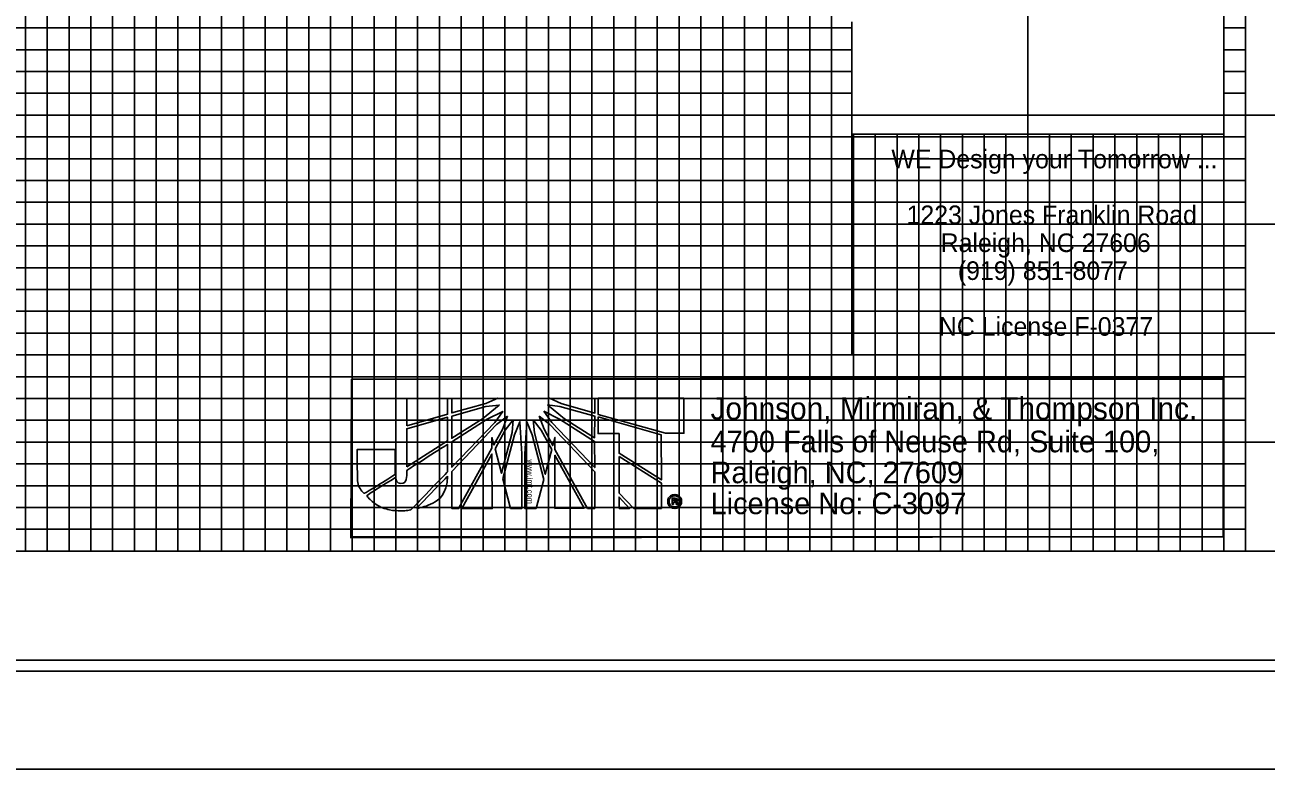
# Model space of a CAD drawing. Extents: x 557032 to 558840, y 515971 to 517218.
# Drawn here: x 558369.3 to 558654.2, y 516118.2 to 516288.9 of the extents above; entities that cross this region are included whole.
import ezdxf

# ---------------------------------------------------------------- set-up
doc = ezdxf.new("R2010")
doc.units = 0
for name, color, linetype in [('Prop DSN Text', 7, 'Continuous'), ('Prop Vertical Profile Grade Label', 7, 'Continuous'), ('Prop VPI Label', 7, 'Continuous'), ('Scratch_Level_5', 7, 'Continuous'), ('Sheet Cutting Line CELL', 7, 'Continuous'), ('Sheet DOT Grid CELL', 7, 'Continuous'), ('Sheet Layout Profile Border Port 2', 7, 'Continuous'), ('Sheet Plot Border Inside CELL', 7, 'Continuous'), ('Sheet Plot Border Outside CELL', 7, 'Continuous'), ('Sheet Profile CELL', 7, 'Continuous'), ('Sheet Profile Grid Major CELL', 7, 'Continuous'), ('Sheet Profile Grid Middle CELL', 7, 'Continuous'), ('Sheet Profile Grid Minor CELL', 7, 'Continuous')]:
    doc.layers.add(name, color=color, linetype=linetype)

msp = doc.modelspace()

# ---------------------------------------------------------------- linework, layer by layer
at = {"layer": 'Prop DSN Text'}
for p, q in [((558559.12, 516213.17), (558559.12, 516289.56)), ((558644.45, 516289.56), (558644.45, 516213.17)), ((558559.12, 516263.76), (558644.45, 516263.76)), ((558644.45, 516213.17), (558559.12, 516213.17))]:
    msp.add_line(p, q, dxfattribs=at)
at = {"layer": 'Prop Vertical Profile Grade Label'}
msp.add_lwpolyline([(558559.12, 516263.76), (558644.45, 516263.76), (558644.45, 516213.17), (558559.12, 516213.17)], close=True, dxfattribs=at)
at = {"layer": 'Prop VPI Label'}
for p, q in [((558466.31, 516203.16), (558456.95, 516203.15)), ((558456.95, 516203.15), (558456.95, 516196.94)), ((558466.31, 516199.54), (558466.31, 516203.16)), ((558477.82, 516203.21), (558467.28, 516203.2)), ((558467.28, 516203.2), (558467.28, 516199.85)), ((558467.28, 516199.85), (558475.13, 516202.02)), ((558475.13, 516202.02), (558477.82, 516203.21)), ((558500.12, 516203.19), (558489.74, 516203.22)), ((558489.74, 516203.22), (558492.37, 516201.99)), ((558492.37, 516201.99), (558500.13, 516199.82)), ((558500.13, 516199.82), (558500.12, 516203.19)), ((558520.53, 516203.25), (558500.85, 516203.24)), ((558500.85, 516203.24), (558500.85, 516199.62)), ((558520.54, 516195.19), (558520.53, 516203.25)), ((558456.95, 516196.94), (558466.31, 516199.54)), ((558475.13, 516201.3), (558467.29, 516199.13)), ((558467.29, 516199.13), (558467.29, 516194.06)), ((558474.31, 516198.51), (558478.19, 516201.67)), ((558478.19, 516201.67), (558475.13, 516201.3)), ((558478.96, 516200.22), (558475.4, 516198.41)), ((558477.16, 516197.68), (558478.96, 516200.22)), ((558480.05, 516199.09), (558477.56, 516197.17)), ((558478.9, 516196.09), (558480.05, 516199.09)), ((558487.31, 516199.1), (558488.45, 516196.1)), ((558489.79, 516197.18), (558487.31, 516199.1)), ((558488.4, 516200.23), (558490.21, 516197.65)), ((558492.02, 516198.42), (558488.4, 516200.23)), ((558489.22, 516201.68), (558493.15, 516198.47)), ((558492.11, 516201.31), (558489.22, 516201.68)), ((558500.13, 516199.11), (558492.11, 516201.31)), ((558500.07, 516194.15), (558500.13, 516199.11)), ((558500.85, 516199.62), (558500.85, 516199.51)), ((558500.85, 516199.51), (558516.35, 516195.19)), ((558500.85, 516198.96), (558500.85, 516198.89)), ((558515.36, 516194.83), (558500.85, 516198.96)), ((558466.31, 516198.86), (558456.95, 516196.23)), ((558456.95, 516196.23), (558456.96, 516187.5)), ((558466.32, 516193.44), (558466.31, 516198.86)), ((558467.29, 516194.06), (558474.31, 516198.51)), ((558475.4, 516198.41), (558467.29, 516193.24)), ((558467.3, 516187.4), (558477.16, 516197.68)), ((558477.56, 516197.17), (558467.3, 516186.41)), ((558476.95, 516192.52), (558478.9, 516196.09)), ((558481.39, 516198.26), (558479.54, 516195.88)), ((558481.13, 516195.37), (558481.39, 516198.26)), ((558482.93, 516197.84), (558481.66, 516194.84)), ((558483.34, 516190.46), (558482.93, 516197.84)), ((558484.48, 516197.84), (558484.01, 516190.46)), ((558485.72, 516194.85), (558484.48, 516197.84)), ((558485.98, 516198.26), (558486.29, 516195.27)), ((558487.79, 516195.89), (558485.98, 516198.26)), ((558488.45, 516196.1), (558490.46, 516192.38)), ((558500.08, 516186.35), (558489.79, 516197.18)), ((558490.21, 516197.65), (558500.08, 516187.32)), ((558500.07, 516193.32), (558492.02, 516198.42)), ((558493.15, 516198.47), (558500.07, 516194.15)), ((558500.85, 516198.89), (558500.86, 516195.13)), ((558456.96, 516187.5), (558466.32, 516193.44)), ((558467.29, 516193.24), (558467.3, 516187.4)), ((558476.48, 516191.75), (558476.48, 516194.22)), ((558476.48, 516194.22), (558476.95, 516192.52)), ((558479.54, 516195.88), (558477.21, 516191.64)), ((558478.71, 516186.02), (558481.13, 516195.37)), ((558481.66, 516194.84), (558479.02, 516184.72)), ((558488.42, 516184.58), (558485.72, 516194.85)), ((558486.29, 516195.27), (558488.72, 516185.81)), ((558490.22, 516191.5), (558487.79, 516195.89)), ((558490.46, 516192.38), (558490.94, 516194.24)), ((558490.94, 516194.24), (558490.94, 516191.5)), ((558500.08, 516187.32), (558500.07, 516193.32)), ((558500.86, 516195.13), (558505.66, 516195.13)), ((558505.66, 516195.13), (558505.67, 516190.63)), ((558515.37, 516184.5), (558515.36, 516194.83)), ((558516.35, 516195.19), (558520.54, 516195.19)), ((558468.85, 516177.92), (558476.48, 516191.75)), ((558476.48, 516190.41), (558469.58, 516177.92)), ((558476.56, 516177.92), (558476.48, 516190.41)), ((558477.21, 516191.64), (558478.71, 516186.02)), ((558483.36, 516177.98), (558483.34, 516190.46)), ((558484.01, 516190.46), (558484.02, 516177.98)), ((558488.72, 516185.81), (558490.22, 516191.5)), ((558490.94, 516191.5), (558498.43, 516177.95)), ((558505.67, 516190.63), (558515.37, 516184.5)), ((558497.66, 516177.99), (558490.94, 516190.16)), ((558490.94, 516190.16), (558490.96, 516177.98)), ((558505.67, 516189.86), (558505.67, 516181.49)), ((558515.37, 516183.77), (558505.67, 516189.86)), ((558467.3, 516186.41), (558467.31, 516177.92)), ((558479.02, 516184.72), (558480.79, 516177.97)), ((558500.09, 516177.95), (558500.08, 516186.35)), ((558486.61, 516177.98), (558488.42, 516184.58)), ((558515.38, 516177.96), (558515.37, 516183.77)), ((558505.67, 516181.49), (558509.03, 516177.96)), ((558508.1, 516177.95), (558505.67, 516180.58)), ((558505.67, 516180.58), (558505.68, 516177.95)), ((558517.84, 516178.85), (558517.84, 516180.28)), ((558517.84, 516180.28), (558518.43, 516180.28)), ((558518.43, 516180.01), (558518.17, 516180.01)), ((558518.17, 516180.01), (558518.17, 516179.67)), ((558518.17, 516179.67), (558518.43, 516179.67)), ((558518.43, 516179.41), (558518.17, 516179.41)), ((558518.17, 516179.41), (558518.17, 516178.85)), ((558518.43, 516181.12), (558518.43, 516180.83)), ((558518.43, 516180.83), (558518.43, 516181.12)), ((558518.43, 516180.28), (558518.43, 516180.01)), ((558518.43, 516180.01), (558518.43, 516180.28)), ((558518.43, 516180.28), (558518.52, 516180.28)), ((558518.47, 516180.01), (558518.43, 516180.01)), ((558518.43, 516179.67), (558518.43, 516179.41)), ((558518.43, 516179.41), (558518.43, 516179.67)), ((558518.43, 516179.67), (558518.44, 516179.67)), ((558518.44, 516179.41), (558518.43, 516179.41)), ((558467.31, 516177.92), (558468.85, 516177.92)), ((558469.58, 516177.92), (558476.56, 516177.92)), ((558480.79, 516177.97), (558483.36, 516177.98)), ((558484.02, 516177.98), (558486.61, 516177.98)), ((558490.96, 516177.98), (558497.66, 516177.99)), ((558498.43, 516177.95), (558500.09, 516177.95)), ((558505.68, 516177.95), (558508.1, 516177.95)), ((558509.03, 516177.96), (558515.38, 516177.96)), ((558518.17, 516178.85), (558517.84, 516178.85)), ((558518.43, 516178.29), (558518.43, 516177.98)), ((558518.43, 516177.98), (558518.43, 516178.29)), ((558518.43, 516178.29), (558518.44, 516178.29)), ((558518.44, 516177.98), (558518.43, 516177.98))]:
    msp.add_line(p, q, dxfattribs=at)
for points in [[(558444.29, 516207.58), (558644.45, 516207.98), (558644.32, 516171.48), (558444.14, 516171.2)], [(558444.29, 516171.48), (558644.32, 516171.48), (558644.32, 516207.58), (558444.29, 516207.58)]]:
    msp.add_lwpolyline(points, close=True, dxfattribs=at)
for points in [[(558456.95, 516196.94), (558466.31, 516199.54), (558466.31, 516203.16), (558456.95, 516203.15), (558456.95, 516196.94)], [(558475.13, 516202.02), (558477.82, 516203.21), (558467.28, 516203.2), (558467.28, 516199.85), (558475.13, 516202.02)], [(558492.37, 516201.99), (558500.13, 516199.82), (558500.12, 516203.19), (558489.74, 516203.22), (558492.37, 516201.99)], [(558520.53, 516203.25), (558500.85, 516203.24), (558500.85, 516199.62), (558500.85, 516199.51), (558516.35, 516195.19), (558520.54, 516195.19), (558520.53, 516203.25)], [(558467.29, 516199.13), (558467.29, 516194.06), (558474.31, 516198.51), (558478.19, 516201.67), (558475.13, 516201.3), (558467.29, 516199.13)], [(558467.29, 516193.24), (558467.3, 516187.4), (558477.16, 516197.68), (558478.96, 516200.22), (558475.4, 516198.41), (558467.29, 516193.24)], [(558480.05, 516199.09), (558477.56, 516197.17), (558467.3, 516186.41), (558467.31, 516177.92), (558468.85, 516177.92), (558476.48, 516191.75), (558476.48, 516194.22), (558476.95, 516192.52), (558478.9, 516196.09), (558480.05, 516199.09)], [(558487.31, 516199.1), (558488.45, 516196.1), (558490.46, 516192.38), (558490.94, 516194.24), (558490.94, 516191.5), (558498.43, 516177.95), (558500.09, 516177.95), (558500.08, 516186.35), (558489.79, 516197.18), (558487.31, 516199.1)], [(558488.4, 516200.23), (558490.21, 516197.65), (558500.08, 516187.32), (558500.07, 516193.32), (558492.02, 516198.42), (558488.4, 516200.23)], [(558489.22, 516201.68), (558493.15, 516198.47), (558500.07, 516194.15), (558500.13, 516199.11), (558492.11, 516201.31), (558489.22, 516201.68)], [(558500.85, 516198.96), (558500.85, 516198.89), (558500.86, 516195.13), (558505.66, 516195.13), (558505.67, 516190.63), (558515.37, 516184.5), (558515.36, 516194.83), (558500.85, 516198.96)], [(558456.96, 516187.5), (558466.32, 516193.44), (558466.31, 516198.86), (558456.95, 516196.23), (558456.96, 516187.5)], [(558481.39, 516198.26), (558479.54, 516195.88), (558477.21, 516191.64), (558478.71, 516186.02), (558481.13, 516195.37), (558481.39, 516198.26)], [(558481.66, 516194.84), (558479.02, 516184.72), (558480.79, 516177.97), (558483.36, 516177.98), (558483.34, 516190.46), (558482.93, 516197.84), (558481.66, 516194.84)], [(558484.48, 516197.84), (558484.01, 516190.46), (558484.02, 516177.98), (558486.61, 516177.98), (558488.42, 516184.58), (558485.72, 516194.85), (558484.48, 516197.84)], [(558485.98, 516198.26), (558486.29, 516195.27), (558488.72, 516185.81), (558490.22, 516191.5), (558487.79, 516195.89), (558485.98, 516198.26)], [(558469.58, 516177.92), (558476.56, 516177.92), (558476.48, 516190.41), (558469.58, 516177.92)], [(558490.96, 516177.98), (558497.66, 516177.99), (558490.94, 516190.16), (558490.96, 516177.98)], [(558505.67, 516189.86), (558505.67, 516181.49), (558509.03, 516177.96), (558515.38, 516177.96), (558515.37, 516183.77), (558505.67, 516189.86), (558505.67, 516189.86)], [(558505.68, 516177.95), (558505.68, 516177.95), (558508.1, 516177.95), (558505.67, 516180.58), (558505.68, 516177.95)], [(558519.05, 516179.19), (558519.05, 516179.11), (558519.06, 516179.06), (558519.06, 516179), (558519.1, 516178.85), (558518.81, 516178.85)]]:
    msp.add_lwpolyline(points, dxfattribs=at)
for points, degree in [([(558454.27, 516191.51), (558454.27, 516191.51), (558445.6, 516191.5), (558445.6, 516191.5), (558445.6, 516191.5), (558445.61, 516186.08), (558445.61, 516186.08), (558445.61, 516186.08), (558445.61, 516185.51), (558445.61, 516185.51), (558445.61, 516183.81), (558446.17, 516182.47), (558447.16, 516181.34), (558447.16, 516181.34), (558454.28, 516185.67), (558454.28, 516185.78), (558454.28, 516185.78), (558454.27, 516191.51), (558454.27, 516191.51)], 3), ([(558455.62, 516183.71), (558455.07, 516183.71), (558454.59, 516184.02), (558454.38, 516185.06), (558454.38, 516185.06), (558447.67, 516180.89), (558447.67, 516180.89), (558449.74, 516178.72), (558453.05, 516177.42), (558455.84, 516177.43), (558456.57, 516177.43), (558457.13, 516177.49), (558457.9, 516177.64), (558457.9, 516177.64), (558466.32, 516186.36), (558466.32, 516186.36), (558466.32, 516186.36), (558466.32, 516192.67), (558466.32, 516192.67), (558466.32, 516192.67), (558456.96, 516186.71), (558456.96, 516186.71), (558456.96, 516184.35), (558456.39, 516183.71), (558455.62, 516183.71)], 3), ([(558455.62, 516183.71), (558455.07, 516183.71), (558454.59, 516184.02), (558454.38, 516185.06), (558454.38, 516185.06), (558447.67, 516180.89), (558447.67, 516180.89), (558449.74, 516178.72), (558453.05, 516177.42), (558455.84, 516177.43), (558456.57, 516177.43), (558457.13, 516177.49), (558457.9, 516177.64), (558457.9, 516177.64), (558466.32, 516186.36), (558466.32, 516186.36), (558466.32, 516186.36), (558466.32, 516192.67), (558466.32, 516192.67), (558466.32, 516192.67), (558456.96, 516186.71), (558456.96, 516186.71), (558456.96, 516184.35), (558456.39, 516183.71), (558455.62, 516183.71)], 3), ([(558466.33, 516185.38), (558466.33, 516185.38), (558459.04, 516177.85), (558459.04, 516177.85), (558462.61, 516178.73), (558466.16, 516181.1), (558466.33, 516185.38)], 3), ([(558518.43, 516177.98), (558518, 516177.98), (558517.62, 516178.13), (558517.31, 516178.44), (558517, 516178.74), (558516.84, 516179.12), (558516.84, 516179.56), (558516.84, 516180), (558517, 516180.38), (558517.31, 516180.67), (558517.62, 516180.97), (558517.98, 516181.12), (558518.43, 516181.12)], 3), ([(558518.43, 516180.83), (558518.07, 516180.83), (558517.78, 516180.71), (558517.53, 516180.47), (558517.28, 516180.23), (558517.15, 516179.91), (558517.15, 516179.56), (558517.15, 516179.21), (558517.28, 516178.9), (558517.53, 516178.65), (558517.78, 516178.41), (558518.08, 516178.29), (558518.43, 516178.29)], 3), ([(558518.43, 516181.12), (558518.87, 516181.13), (558519.25, 516180.97), (558519.56, 516180.67), (558519.87, 516180.38), (558520.03, 516180.01), (558520.03, 516179.57)], 3), ([(558518.44, 516178.29), (558518.79, 516178.29), (558519.09, 516178.41), (558519.34, 516178.65), (558519.59, 516178.9), (558519.72, 516179.21), (558519.72, 516179.56), (558519.71, 516179.92), (558519.58, 516180.23), (558519.34, 516180.48), (558519.09, 516180.71), (558518.79, 516180.83), (558518.43, 516180.83)], 3), ([(558518.44, 516179.67), (558518.65, 516179.67), (558518.75, 516179.73), (558518.75, 516179.85), (558518.75, 516179.95), (558518.66, 516180.01), (558518.47, 516180.01)], 3), ([(558520.03, 516179.57), (558520.03, 516179.12), (558519.87, 516178.75), (558519.57, 516178.43), (558519.26, 516178.13), (558518.88, 516177.98), (558518.44, 516177.98)], 3), ([(558518.69, 516179.36), (558518.65, 516179.38), (558518.57, 516179.41), (558518.44, 516179.41)], 2), ([(558518.52, 516180.28), (558518.88, 516180.28), (558519.06, 516180.14), (558519.06, 516179.85), (558519.06, 516179.72), (558519.01, 516179.62), (558518.9, 516179.54)], 3), ([(558518.81, 516178.85), (558518.77, 516178.93), (558518.74, 516179), (558518.74, 516179.11), (558518.74, 516179.24), (558518.73, 516179.32), (558518.69, 516179.36)], 3), ([(558518.9, 516179.54), (558518.99, 516179.49), (558519.04, 516179.37), (558519.05, 516179.19)], 2)]:
    msp.add_open_spline(points, degree=degree, dxfattribs=at)
at = {"layer": 'Scratch_Level_5'}
msp.add_lwpolyline([(558074.45, 516168.17), (558699.34, 516168.17), (558699.34, 516568.17), (558074.45, 516568.17)], close=True, dxfattribs=at)
at = {"layer": 'Sheet Cutting Line CELL'}
msp.add_line((557032.45, 516118.17), (558716.45, 516118.17), dxfattribs=at)
at = {"layer": 'Sheet DOT Grid CELL'}
for p, q in [((558399.45, 516668.17), (558399.45, 516168.17)), ((558449.45, 516668.17), (558449.45, 516168.17)), ((558499.45, 516668.17), (558499.45, 516168.17)), ((558549.45, 516668.17), (558549.45, 516168.17)), ((558599.45, 516668.17), (558599.45, 516168.17)), ((558649.45, 516668.17), (558649.45, 516168.17)), ((557199.45, 516268.17), (558699.34, 516268.17)), ((557199.45, 516218.17), (558699.34, 516218.17))]:
    msp.add_line(p, q, dxfattribs=at)
at = {"layer": 'Sheet Layout Profile Border Port 2'}
msp.add_lwpolyline([(557249.45, 516668.17), (558649.45, 516668.17), (558649.45, 516168.17), (557249.45, 516168.17)], close=True, dxfattribs=at)
at = {"layer": 'Sheet Plot Border Inside CELL'}
msp.add_lwpolyline([(557045.45, 516140.62), (558711.95, 516140.62), (558711.95, 517195.72), (557045.45, 517195.72)], close=True, dxfattribs=at)
at = {"layer": 'Sheet Plot Border Outside CELL'}
msp.add_lwpolyline([(557032.45, 516118.17), (558716.45, 516118.17), (558716.45, 517218.17), (557032.45, 517218.17)], close=True, dxfattribs=at)
at = {"layer": 'Sheet Profile CELL'}
for p, q in [((558699.45, 516168.17), (557199.45, 516168.17)), ((557199.45, 516143.17), (558699.45, 516143.17))]:
    msp.add_line(p, q, dxfattribs=at)
msp.add_lwpolyline([(558699.45, 517193.17), (557199.45, 517193.17), (557199.45, 516143.17), (558699.45, 516143.17)], close=True, dxfattribs=at)
at = {"layer": 'Sheet Profile Grid Major CELL'}
msp.add_line((558599.45, 516168.17), (558599.45, 516168.17), dxfattribs=at)
for points in [[(558349.45, 516168.17), (558399.45, 516168.17), (558399.45, 516668.17), (558449.45, 516668.17), (558449.45, 516168.17), (558499.45, 516168.17), (558499.45, 516668.17), (558549.45, 516668.17), (558549.45, 516168.17), (558599.45, 516168.17), (558599.45, 516168.17), (558599.45, 516263.76)], [(558599.45, 516289.56), (558599.45, 516668.17), (558649.45, 516668.17), (558649.45, 516168.17)], [(558559.12, 516268.17), (557199.45, 516268.17), (557199.45, 516268.17), (557199.45, 516218.17), (558699.45, 516218.17)], [(558699.45, 516268.17), (558644.45, 516268.17)], [(558699.45, 516168.17), (557199.45, 516168.17)]]:
    msp.add_lwpolyline(points, dxfattribs=at)
at = {"layer": 'Sheet Profile Grid Middle CELL'}
for p, q in [((558374.45, 516668.17), (558374.45, 516168.17)), ((558424.45, 516168.17), (558424.45, 516668.17)), ((558474.45, 516668.17), (558474.45, 516168.17)), ((558524.45, 516168.17), (558524.45, 516668.17)), ((558574.45, 516263.76), (558574.45, 516168.17)), ((558624.45, 516168.17), (558624.45, 516263.76)), ((558374.45, 516168.17), (558424.45, 516168.17)), ((558474.45, 516168.17), (558524.45, 516168.17)), ((558574.45, 516168.17), (558624.45, 516168.17))]:
    msp.add_line(p, q, dxfattribs=at)
for points in [[(558699.45, 516293.17), (557199.45, 516293.17), (557199.45, 516243.17), (558699.45, 516243.17)], [(558699.45, 516193.17), (557199.45, 516193.17)]]:
    msp.add_lwpolyline(points, dxfattribs=at)
at = {"layer": 'Sheet Profile Grid Minor CELL'}
for p, q in [((557249.45, 516288.17), (558559.12, 516288.17)), ((558644.45, 516288.17), (558649.45, 516288.17)), ((558559.12, 516283.17), (557249.45, 516283.17)), ((558649.45, 516283.17), (558644.45, 516283.17)), ((557249.45, 516278.17), (558559.12, 516278.17)), ((558644.45, 516278.17), (558649.45, 516278.17)), ((558559.12, 516273.17), (557249.45, 516273.17)), ((558649.45, 516273.17), (558644.45, 516273.17)), ((557249.45, 516263.17), (558649.45, 516263.17)), ((558649.45, 516258.17), (557249.45, 516258.17)), ((557249.45, 516253.17), (558649.45, 516253.17)), ((558649.45, 516248.17), (557249.45, 516248.17)), ((557249.45, 516238.17), (558649.45, 516238.17)), ((558649.45, 516233.17), (557249.45, 516233.17)), ((557249.45, 516228.17), (558649.45, 516228.17)), ((558649.45, 516223.17), (557249.45, 516223.17)), ((557249.45, 516213.17), (558649.45, 516213.17)), ((558649.45, 516208.17), (557249.45, 516208.17)), ((557249.45, 516203.17), (558649.45, 516203.17)), ((558649.45, 516198.17), (557249.45, 516198.17)), ((557249.45, 516188.17), (558649.45, 516188.17)), ((558649.45, 516183.17), (557249.45, 516183.17)), ((557249.45, 516178.17), (558649.45, 516178.17)), ((557249.45, 516173.17), (558649.45, 516173.17)), ((558649.45, 516173.17), (558649.45, 516173.17))]:
    msp.add_line(p, q, dxfattribs=at)
for points in [[(558364.45, 516168.17), (558369.45, 516168.17), (558369.45, 516668.17), (558379.45, 516668.17), (558379.45, 516168.17), (558384.45, 516168.17), (558384.45, 516668.17), (558389.45, 516668.17), (558389.45, 516168.17)], [(558389.45, 516168.17), (558394.45, 516168.17), (558394.45, 516668.17)], [(558404.45, 516668.17), (558404.45, 516168.17), (558409.45, 516168.17), (558409.45, 516668.17)], [(558414.45, 516668.17), (558414.45, 516168.17), (558419.45, 516168.17), (558419.45, 516668.17)], [(558429.45, 516668.17), (558429.45, 516168.17), (558434.45, 516168.17), (558434.45, 516668.17)], [(558439.45, 516668.17), (558439.45, 516168.17), (558444.45, 516168.17), (558444.45, 516668.17)], [(558454.45, 516668.17), (558454.45, 516168.17), (558459.45, 516168.17), (558459.45, 516668.17)], [(558464.45, 516668.17), (558464.45, 516168.17), (558469.45, 516168.17), (558469.45, 516668.17)], [(558479.45, 516668.17), (558479.45, 516168.17), (558484.45, 516168.17), (558484.45, 516668.17)], [(558489.45, 516668.17), (558489.45, 516168.17), (558494.45, 516168.17), (558494.45, 516668.17)], [(558504.45, 516668.17), (558504.45, 516168.17), (558509.45, 516168.17), (558509.45, 516668.17)], [(558514.45, 516668.17), (558514.45, 516168.17), (558519.45, 516168.17), (558519.45, 516668.17)], [(558529.45, 516668.17), (558529.45, 516168.17), (558534.45, 516168.17), (558534.45, 516668.17)], [(558539.45, 516668.17), (558539.45, 516168.17), (558544.45, 516168.17), (558544.45, 516668.17)], [(558554.45, 516668.17), (558554.45, 516168.17), (558559.45, 516168.17), (558559.45, 516263.76)], [(558639.45, 516263.76), (558639.45, 516168.17), (558644.45, 516168.17), (558644.45, 516668.17), (558649.45, 516668.17)], [(558564.45, 516263.76), (558564.45, 516168.17), (558569.45, 516168.17), (558569.45, 516263.76)], [(558579.45, 516263.76), (558579.45, 516168.17), (558584.45, 516168.17), (558584.45, 516263.76)], [(558589.45, 516263.76), (558589.45, 516168.17), (558594.45, 516168.17), (558594.45, 516263.76)], [(558604.45, 516263.76), (558604.45, 516168.17), (558609.45, 516168.17), (558609.45, 516263.76)], [(558614.45, 516263.76), (558614.45, 516168.17), (558619.45, 516168.17), (558619.45, 516263.76)], [(558629.45, 516263.76), (558629.45, 516168.17), (558634.45, 516168.17), (558634.45, 516263.76)]]:
    msp.add_lwpolyline(points, dxfattribs=at)

# ---------------------------------------------------------------- texts
at = {"layer": 'Prop DSN Text'}
for s, p in [('WE Design your Tomorrow ...', (558568.16, 516255.96)), ('1223 Jones Franklin Road', (558571.65, 516243.16)), ('Raleigh, NC 27606', (558579.47, 516236.76)), ('(919) 851-8077', (558583.41, 516230.36)), ('NC License F-0377', (558579.06, 516217.56))]:
    msp.add_text(s, height=4.2667, rotation=0, dxfattribs=at).set_placement(p)
at = {"layer": 'Prop VPI Label'}
for s, height, p in [('Johnson, Mirmiran, & Thompson Inc.', 5.1112, (558526.67, 516198.33)), ('4700 Falls of Neuse Rd, Suite 100, ', 4.9652, (558526.67, 516190.83)), ('Raleigh, NC, 27609', 4.9652, (558526.67, 516183.74)), ('License No: C-3097', 4.9652, (558526.67, 516176.64))]:
    msp.add_text(s, height=height, dxfattribs=at).set_placement(p)
msp.add_text('www.jmt.com', height=1.2413, rotation=270, dxfattribs=at).set_placement((558484.64, 516189.19))

doc.saveas('drawing.dxf')
